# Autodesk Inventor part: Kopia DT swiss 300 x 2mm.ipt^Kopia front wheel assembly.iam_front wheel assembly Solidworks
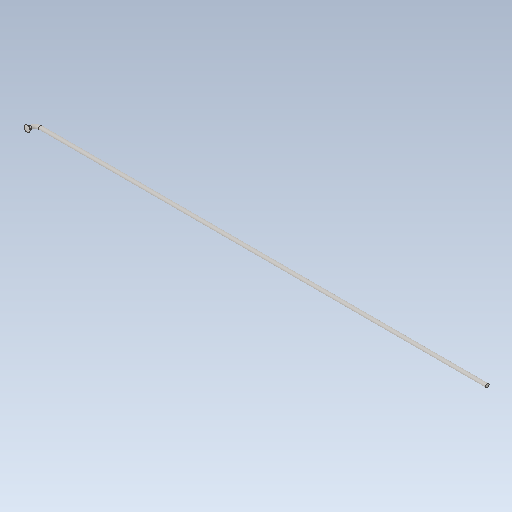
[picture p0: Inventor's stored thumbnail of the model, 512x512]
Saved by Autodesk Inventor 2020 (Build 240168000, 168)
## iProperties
Created: 2017-09
Part Number: Kopia DT swiss 300 x 2mm.ipt^Kopia front wheel assembly.iam_front wheel assembly Solidworks
Material: Ogólny
Document SubType Name: Modeling
Designer: Tomasz
Density: 1 g/cm^3
Appearance: Domyślna
Sending System: SolidWorks 2017
Last Author: Tomasz
Last Saved: 2017-09-11
Author: Tomasz
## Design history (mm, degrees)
feature "DT swiss 300 x 2mm.ipt"
node "Bryła1"
